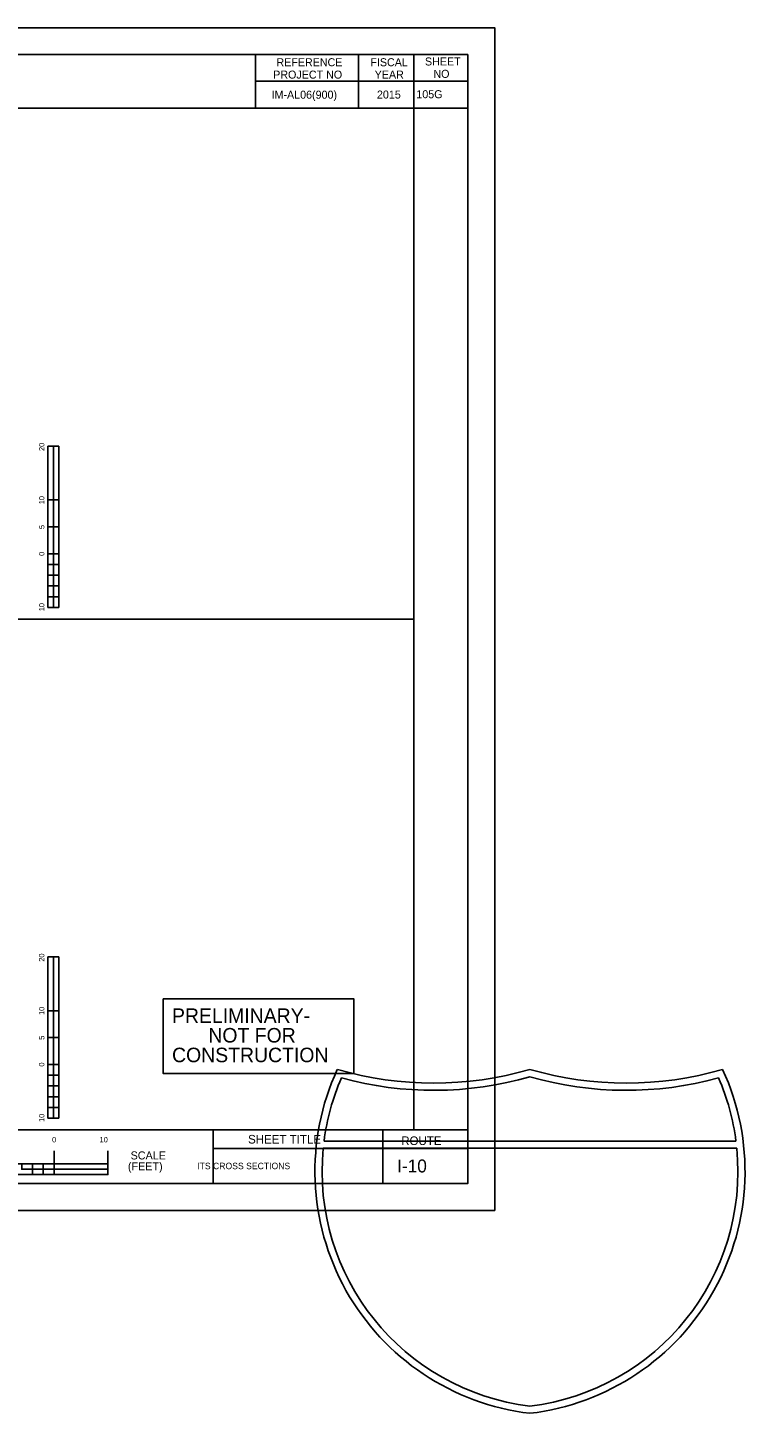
# Model space of a CAD drawing. Extents: x 2193008 to 2198143, y 1236112 to 1237864.
# Drawn here: x 2195457 to 2195592.2, y 1237080.3 to 1237338 of the extents above; entities that cross this region are included whole.
import ezdxf

# ---------------------------------------------------------------- set-up
doc = ezdxf.new("R2010")
doc.units = 0
for name, color, linetype in [('1', 7, 'Continuous'), ('2', 7, 'Continuous'), ('3', 7, 'Continuous'), ('ANNO-SHT', 7, 'Continuous'), ('ANNO-SYMB', 7, 'Continuous'), ('ANNO-TXT', 7, 'Continuous'), ('GSOUTLINE', 7, 'Continuous'), ('Level 1', 7, 'Continuous'), ('Level 6', 7, 'Continuous'), ('Level 62', 7, 'Continuous'), ('SHT-BDR', 7, 'Continuous'), ('SHT-BNDRY', 7, 'Continuous')]:
    doc.layers.add(name, color=color, linetype=linetype)

msp = doc.modelspace()

# ---------------------------------------------------------------- linework, layer by layer
at = {"layer": '1'}
msp.add_lwpolyline([(2195482.11, 1237157.4), (2195517.57, 1237157.4), (2195517.57, 1237143.51), (2195482.11, 1237143.51)], close=True, dxfattribs=at)
at = {"layer": '2'}
msp.add_lwpolyline([(2195528.75, 1237281.19), (2195528.76, 1237280.19)], dxfattribs=at)
msp.add_lwpolyline([(2195528.75, 1237281.19), (2195528.76, 1237280.19)], dxfattribs=at)
at = {"layer": '3'}
msp.add_line((2195228.78, 1237228.05), (2195528.78, 1237228.05), dxfattribs=at)
at = {"layer": 'ANNO-SYMB'}
for p, q in [((2195461.85, 1237124.7), (2195461.85, 1237129.1)), ((2195461.85, 1237124.7), (2195461.85, 1237129.1)), ((2195461.85, 1237124.7), (2195461.85, 1237129.1)), ((2195471.85, 1237124.7), (2195471.85, 1237129.1)), ((2195471.85, 1237126.7), (2195451.85, 1237126.7)), ((2195471.85, 1237124.7), (2195451.85, 1237124.7)), ((2195461.85, 1237125.7), (2195457.85, 1237125.7)), ((2195461.85, 1237125.7), (2195461.85, 1237126.7)), ((2195461.85, 1237125.7), (2195461.85, 1237126.7)), ((2195461.85, 1237125.7), (2195461.85, 1237126.7)), ((2195471.85, 1237124.7), (2195471.85, 1237125.7)), ((2195471.85, 1237124.7), (2195471.85, 1237125.7)), ((2195471.85, 1237124.7), (2195471.85, 1237125.7))]:
    msp.add_line(p, q, dxfattribs=at)
for points in [[(2195455.85, 1237126.7), (2195457.85, 1237126.7), (2195457.85, 1237125.7), (2195455.85, 1237125.7)], [(2195457.85, 1237125.7), (2195459.85, 1237125.7), (2195459.85, 1237124.7), (2195457.85, 1237124.7)], [(2195459.85, 1237126.7), (2195461.85, 1237126.7), (2195461.85, 1237125.7), (2195459.85, 1237125.7)], [(2195461.85, 1237125.7), (2195471.85, 1237125.7), (2195471.85, 1237124.7), (2195461.85, 1237124.7)]]:
    msp.add_lwpolyline(points, close=True, dxfattribs=at)
at = {"layer": 'ANNO-TXT'}
for p, q in [((2195491.45, 1237129.57), (2195522.97, 1237129.57)), ((2195522.97, 1237129.57), (2195538.79, 1237129.57))]:
    msp.add_line(p, q, dxfattribs=at)
at = {"layer": 'GSOUTLINE'}
for points in [[(2195511.9, 1237129.61), (2195588.79, 1237129.61)], [(2195588.64, 1237130.95), (2195512.06, 1237130.95)]]:
    msp.add_lwpolyline(points, dxfattribs=at)
for centre, major_axis, start_param, end_param in [((2195555.68, 1237125.3), (45.32, 0), 2.709569, 4.594469), ((2195555.68, 1237125.3), (43.99, 0), 2.735396, 3.01287), ((2195532.44, 1237205.68), (63.98, 0), 4.428637, 4.996141), ((2195532.44, 1237205.68), (65.31, 0), 4.446475, 4.990194), ((2195568.26, 1237205.68), (63.98, 0), 4.428637, 4.996141), ((2195545.02, 1237125.3), (45.32, 0), 4.830309, 6.715209), ((2195568.26, 1237205.68), (65.31, 0), 4.434584, 4.978303), ((2195545.02, 1237125.3), (43.99, 0), 0.128722, 0.406196), ((2195555.68, 1237125.3), (43.99, 0), 3.043371, 4.590878), ((2195545.02, 1237125.3), (43.99, 0), 4.8339, 6.381407)]:
    msp.add_ellipse(centre, major_axis=major_axis, ratio=0.999829, start_param=start_param, end_param=end_param, dxfattribs=at)
at = {"layer": 'Level 1'}
for p, q in [((2195460.72, 1237260.19), (2195460.72, 1237230.19)), ((2195462.72, 1237260.19), (2195460.72, 1237260.19)), ((2195462.72, 1237260.19), (2195462.72, 1237250.19)), ((2195462.72, 1237260.19), (2195462.72, 1237230.19)), ((2195461.72, 1237250.19), (2195460.72, 1237250.19)), ((2195462.72, 1237250.19), (2195460.72, 1237250.19)), ((2195461.72, 1237250.19), (2195461.72, 1237245.19)), ((2195462.72, 1237245.19), (2195460.72, 1237245.19)), ((2195462.72, 1237245.19), (2195461.72, 1237245.19)), ((2195462.72, 1237245.19), (2195462.72, 1237240.19)), ((2195461.72, 1237240.19), (2195460.72, 1237240.19)), ((2195462.72, 1237240.19), (2195460.72, 1237240.19)), ((2195461.72, 1237240.19), (2195461.72, 1237238.19)), ((2195462.72, 1237238.19), (2195461.72, 1237238.19)), ((2195462.72, 1237238.19), (2195462.72, 1237236.19)), ((2195461.72, 1237236.19), (2195460.72, 1237236.19)), ((2195461.72, 1237236.19), (2195461.72, 1237234.19)), ((2195462.72, 1237234.19), (2195461.72, 1237234.19)), ((2195462.72, 1237234.19), (2195462.72, 1237232.19)), ((2195461.72, 1237232.19), (2195460.72, 1237232.19)), ((2195462.72, 1237230.19), (2195460.72, 1237230.19)), ((2195461.72, 1237232.19), (2195461.72, 1237230.19)), ((2195460.72, 1237165.19), (2195460.72, 1237135.19)), ((2195462.72, 1237165.19), (2195460.72, 1237165.19)), ((2195462.72, 1237165.19), (2195462.72, 1237155.19)), ((2195462.72, 1237165.19), (2195462.72, 1237135.19)), ((2195461.72, 1237155.19), (2195460.72, 1237155.19)), ((2195462.72, 1237155.19), (2195460.72, 1237155.19)), ((2195461.72, 1237155.19), (2195461.72, 1237150.19)), ((2195462.72, 1237150.19), (2195460.72, 1237150.19)), ((2195462.72, 1237150.19), (2195461.72, 1237150.19)), ((2195462.72, 1237150.19), (2195462.72, 1237145.19)), ((2195461.72, 1237145.19), (2195460.72, 1237145.19)), ((2195462.72, 1237145.19), (2195460.72, 1237145.19)), ((2195461.72, 1237145.19), (2195461.72, 1237143.19)), ((2195462.72, 1237143.19), (2195461.72, 1237143.19)), ((2195462.72, 1237143.19), (2195462.72, 1237141.19)), ((2195461.72, 1237141.19), (2195460.72, 1237141.19)), ((2195461.72, 1237141.19), (2195461.72, 1237139.19)), ((2195461.72, 1237137.19), (2195460.72, 1237137.19)), ((2195462.72, 1237139.19), (2195461.72, 1237139.19)), ((2195461.72, 1237137.19), (2195461.72, 1237135.19)), ((2195462.72, 1237139.19), (2195462.72, 1237137.19)), ((2195462.72, 1237135.19), (2195460.72, 1237135.19))]:
    msp.add_line(p, q, dxfattribs=at)
for points in [[(2195461.72, 1237250.19), (2195461.72, 1237260.19), (2195462.72, 1237260.19), (2195462.72, 1237250.19)], [(2195460.72, 1237245.19), (2195460.72, 1237250.19), (2195461.72, 1237250.19), (2195461.72, 1237245.19)], [(2195461.72, 1237240.19), (2195461.72, 1237245.19), (2195462.72, 1237245.19), (2195462.72, 1237240.19)], [(2195460.72, 1237238.19), (2195460.72, 1237240.19), (2195461.72, 1237240.19), (2195461.72, 1237238.19)], [(2195461.72, 1237236.19), (2195461.72, 1237238.19), (2195462.72, 1237238.19), (2195462.72, 1237236.19)], [(2195460.72, 1237234.19), (2195460.72, 1237236.19), (2195461.72, 1237236.19), (2195461.72, 1237234.19)], [(2195461.72, 1237232.19), (2195461.72, 1237234.19), (2195462.72, 1237234.19), (2195462.72, 1237232.19)], [(2195460.72, 1237230.19), (2195460.72, 1237232.19), (2195461.72, 1237232.19), (2195461.72, 1237230.19)], [(2195461.72, 1237155.19), (2195461.72, 1237165.19), (2195462.72, 1237165.19), (2195462.72, 1237155.19)], [(2195460.72, 1237150.19), (2195460.72, 1237155.19), (2195461.72, 1237155.19), (2195461.72, 1237150.19)], [(2195461.72, 1237145.19), (2195461.72, 1237150.19), (2195462.72, 1237150.19), (2195462.72, 1237145.19)], [(2195460.72, 1237143.19), (2195460.72, 1237145.19), (2195461.72, 1237145.19), (2195461.72, 1237143.19)], [(2195461.72, 1237141.19), (2195461.72, 1237143.19), (2195462.72, 1237143.19), (2195462.72, 1237141.19)], [(2195460.72, 1237139.19), (2195460.72, 1237141.19), (2195461.72, 1237141.19), (2195461.72, 1237139.19)], [(2195460.72, 1237135.19), (2195460.72, 1237137.19), (2195461.72, 1237137.19), (2195461.72, 1237135.19)], [(2195461.72, 1237137.19), (2195461.72, 1237139.19), (2195462.72, 1237139.19), (2195462.72, 1237137.19)]]:
    msp.add_lwpolyline(points, close=True, dxfattribs=at)
at = {"layer": 'Level 6'}
for p, q in [((2195499.33, 1237333.04), (2195499.33, 1237323.05)), ((2195518.49, 1237328.04), (2195518.49, 1237333.04)), ((2195528.78, 1237328.17), (2195528.78, 1237333.04)), ((2195538.79, 1237328.1), (2195499.33, 1237328.1)), ((2195518.49, 1237328.04), (2195518.49, 1237323.05)), ((2195528.78, 1237328.17), (2195528.78, 1237323.05)), ((2195538.79, 1237323.05), (2195500.54, 1237323.05)), ((2195538.79, 1237133.05), (2195491.45, 1237133.05))]:
    msp.add_line(p, q, dxfattribs=at)
at = {"layer": 'Level 62'}
msp.add_lwpolyline([(2195203.79, 1237118.04), (2195543.79, 1237118.04), (2195543.79, 1237338.04), (2195203.79, 1237338.04)], close=True, dxfattribs=at)
at = {"layer": 'SHT-BDR'}
msp.add_lwpolyline([(2195228.78, 1237133.05), (2195528.78, 1237133.05), (2195528.78, 1237323.05), (2195228.78, 1237323.05)], close=True, dxfattribs=at)
at = {"layer": 'SHT-BNDRY'}
for p, q in [((2195491.45, 1237123.04), (2195491.45, 1237133.05)), ((2195522.97, 1237123.04), (2195522.97, 1237133.05))]:
    msp.add_line(p, q, dxfattribs=at)
msp.add_lwpolyline([(2195216.29, 1237123.04), (2195538.79, 1237123.04), (2195538.79, 1237333.04), (2195216.29, 1237333.04)], close=True, dxfattribs=at)

# ---------------------------------------------------------------- texts
at = {"layer": '1'}
for s, p in [('PRELIMINARY-', (2195483.78, 1237152.92)), ('NOT FOR', (2195490.54, 1237149.27)), ('CONSTRUCTION', (2195483.79, 1237145.61))]:
    msp.add_text(s, height=2.7, dxfattribs=at).set_placement(p)
at = {"layer": 'ANNO-SHT'}
for s, height, p in [(' IM-AL06(900) ', 1.4899, (2195501.74, 1237324.83)), ('2015', 1.49, (2195521.89, 1237324.86)), ('  105G ', 1.49, (2195528.11, 1237324.92)), ('          ITS CROSS SECTIONS          ', 1.2, (2195484.01, 1237125.71)), (' I-10 ', 2.4, (2195524.75, 1237125.11))]:
    msp.add_text(s, height=height, rotation=360, dxfattribs=at).set_placement(p)
at = {"layer": 'ANNO-SYMB'}
for s, height, p in [('0', 1, (2195461.48, 1237130.7)), ('0', 1, (2195461.48, 1237130.7)), ('0', 1, (2195461.48, 1237130.7)), (' 10', 0.999, (2195469.93, 1237130.7)), ('(FEET)', 1.499, (2195475.58, 1237125.49)), ('SCALE', 1.499, (2195476.08, 1237127.52))]:
    msp.add_text(s, height=height, rotation=0.0572, dxfattribs=at).set_placement(p)
at = {"layer": 'ANNO-TXT'}
for s, p in [('SHEET TITLE', (2195497.93, 1237130.48)), ('ROUTE', (2195526.41, 1237130.2))]:
    msp.add_text(s, height=1.6, dxfattribs=at).set_placement(p)
at = {"layer": 'Level 1'}
for s, height, p in [('20', 0.999, (2195460.05, 1237259.3)), ('10', 0.999, (2195460.05, 1237249.39)), ('5', 1, (2195460.05, 1237244.78)), ('0', 1, (2195460.05, 1237239.79)), ('10', 0.999, (2195460.05, 1237229.49)), ('20', 0.999, (2195460.05, 1237164.3)), ('10', 0.999, (2195460.05, 1237154.39)), ('5', 1, (2195460.05, 1237149.78)), ('0', 1, (2195460.05, 1237144.79)), ('10', 0.999, (2195460.05, 1237134.49))]:
    msp.add_text(s, height=height, rotation=90.0572, dxfattribs=at).set_placement(p)
at = {"layer": 'Level 6'}
for s, p in [('REFERENCE', (2195503.2, 1237330.87)), ('FISCAL', (2195520.67, 1237330.87)), ('SHEET', (2195530.82, 1237331.01)), ('PROJECT NO', (2195502.6, 1237328.57)), ('YEAR', (2195521.47, 1237328.57)), ('NO', (2195532.39, 1237328.71))]:
    msp.add_text(s, height=1.488, dxfattribs=at).set_placement(p)

doc.saveas('drawing.dxf')
